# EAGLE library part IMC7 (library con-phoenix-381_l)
Invertierter Mini-Combicon 3.81mm horizontal 7-polig IMC 1,5/7-G-3,81 (ohne Gegenstecker)
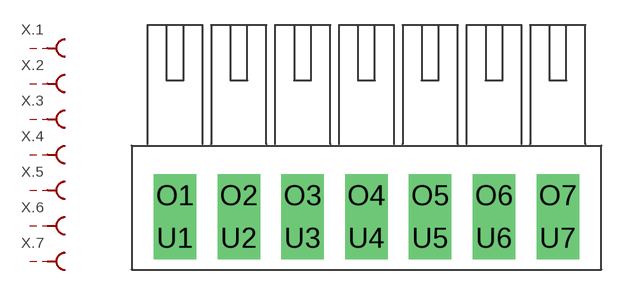
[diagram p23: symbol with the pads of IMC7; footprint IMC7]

Designator prefix X; gates .4=MCBU .3=MCBU .2=MCBU .1=MCBU .5=MCBU .6=MCBU .7=MCBU

## IMC7  [IMC7]
O1  .1:S  pas
O2  .2:S  pas
O3  .3:S  pas
O4  .4:S  pas
O5  .5:S  pas
O6  .6:S  pas
O7  .7:S  pas
U1  .1:SK  pas
U2  .2:SK  pas
U3  .3:SK  pas
U4  .4:SK  pas
U5  .5:SK  pas
U6  .6:SK  pas
U7  .7:SK  pas

## Footprint IMC7 (pad centres in mm)
Mini-Combicon 3.81mm horizontal 7-polig invertiert (ohne Gegenstecker)
drill 1.3 pad 2.54 square: O1 -11.43,1.27; O2 -7.62,1.27; O3 -3.81,1.27; O4 0,1.27; O5 3.81,1.27; O6 7.62,1.27; O7 11.43,1.27; U1 -11.43,-1.27; U2 -7.62,-1.27; U3 -3.81,-1.27; U4 0,-1.27; U5 3.81,-1.27; U6 7.62,-1.27; U7 11.43,-1.27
